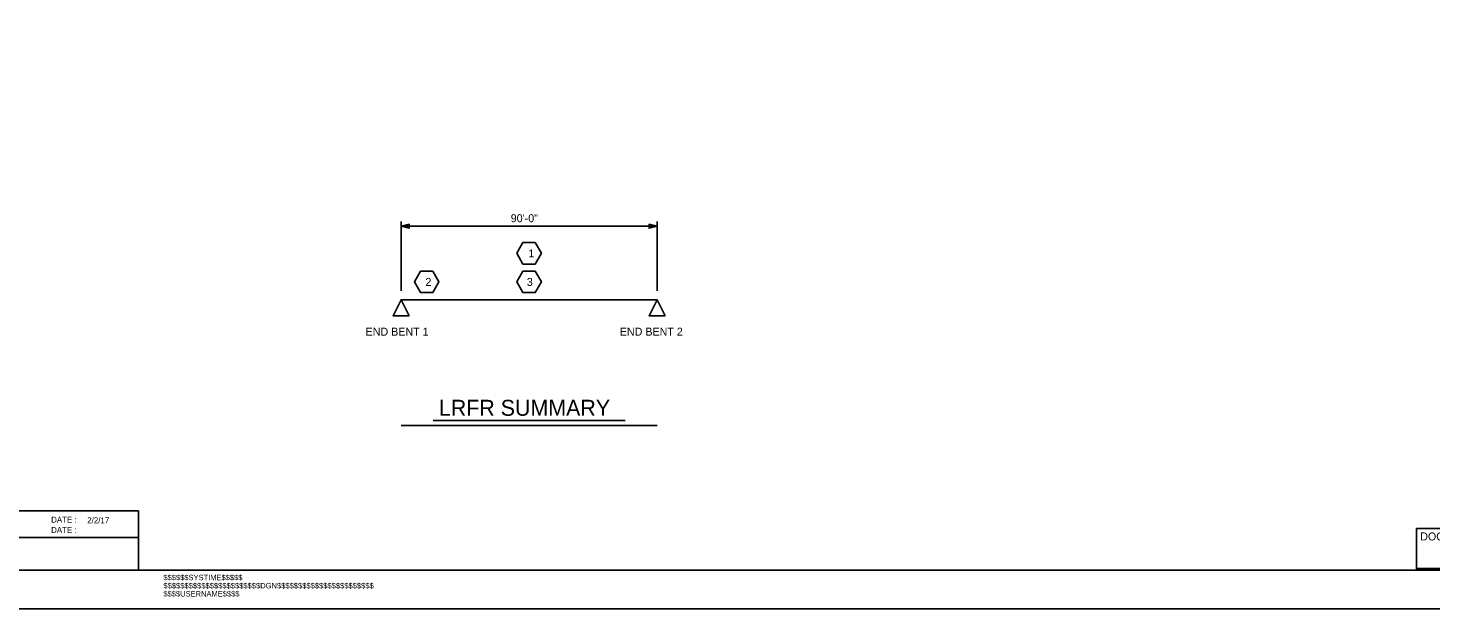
# Model space of a CAD drawing. Extents: x -169 to 381, y 285 to 620.
# Drawn here: x 28.2 to 247.3, y 284.7 to 375.4 of the extents above; entities that cross this region are included whole.
import ezdxf

# ---------------------------------------------------------------- set-up
doc = ezdxf.new("R2010")
doc.units = 0
for name, color, linetype in [('Arrowhead Terminators', 7, 'Continuous'), ('Dimension Lines', 7, 'Continuous'), ('Mis Object Lines', 7, 'Continuous'), ('Plan Sheet', 7, 'Continuous'), ('Plan Sheet CELL', 7, 'Continuous'), ('Plot Label CELL', 7, 'Continuous'), ('Plot Shape CELL', 7, 'Continuous'), ('Sheet Sticker Exception Certification CELL', 7, 'Continuous'), ('Sub End Bent Cap Lines CELL', 7, 'Continuous'), ('Table Border', 7, 'Continuous'), ('Text', 7, 'Continuous'), ('Title Text', 7, 'Continuous')]:
    doc.layers.add(name, color=color, linetype=linetype)

# ---------------------------------------------------------------- blocks, each defined once
blk = doc.blocks.new('AH')
at = {"layer": 'Sub End Bent Cap Lines CELL'}
blk.add_lwpolyline([(0, 0), (-1.25, 0.31), (-1.25, -0.31)], close=True, dxfattribs=at)

msp = doc.modelspace()

# ---------------------------------------------------------------- linework, layer by layer
at = {"layer": 'Dimension Lines'}
for p, q in [((86.45, 334.35), (86.45, 345.18)), ((86.45, 344.43), (126.45, 344.43)), ((126.45, 334.35), (126.45, 345.18))]:
    msp.add_line(p, q, dxfattribs=at)
at = {"layer": 'Mis Object Lines'}
msp.add_line((86.45, 332.96), (126.45, 332.96), dxfattribs=at)
for points in [[(87.7, 330.46), (85.2, 330.46), (86.45, 332.96)], [(127.7, 330.46), (125.2, 330.46), (126.45, 332.96)]]:
    msp.add_lwpolyline(points, close=True, dxfattribs=at)
at = {"layer": 'Plan Sheet'}
for p, q in [((3.77, 299.98), (45.41, 299.98)), ((45.41, 290.71), (45.41, 299.98)), ((45.41, 299.98), (45.41, 299.98)), ((45.41, 295.8), (3.77, 295.8))]:
    msp.add_line(p, q, dxfattribs=at)
at = {"layer": 'Plan Sheet CELL'}
msp.add_line((3.77, 290.71), (323.78, 290.71), dxfattribs=at)
at = {"layer": 'Plot Shape CELL'}
msp.add_lwpolyline([(-6.77, 504.65), (323.86, 504.65), (323.86, 284.65), (-6.77, 284.65)], close=True, dxfattribs=at)
at = {"layer": 'Sheet Sticker Exception Certification CELL'}
msp.add_lwpolyline([(245.07, 297.23), (273.56, 297.23), (273.56, 290.96), (245.07, 290.96)], close=True, dxfattribs=at)
at = {"layer": 'Table Border'}
for points in [[(107.41, 341.87), (105.49, 341.87), (104.53, 340.2), (105.49, 338.53), (107.41, 338.53), (108.37, 340.2)], [(91.41, 337.4), (89.49, 337.4), (88.53, 335.74), (89.49, 334.07), (91.41, 334.07), (92.37, 335.74)], [(107.41, 337.4), (105.49, 337.4), (104.53, 335.74), (105.49, 334.07), (107.41, 334.07), (108.37, 335.74)]]:
    msp.add_lwpolyline(points, close=True, dxfattribs=at)
at = {"layer": 'Title Text'}
for p, q in [((121.45, 314.07), (91.45, 314.07)), ((126.45, 313.32), (86.45, 313.32))]:
    msp.add_line(p, q, dxfattribs=at)

# ---------------------------------------------------------------- block references
at = {"layer": 'Arrowhead Terminators', "rotation": 180}
msp.add_blockref('AH', (86.45, 344.43), dxfattribs=at)
at = {"layer": 'Arrowhead Terminators'}
msp.add_blockref('AH', (126.45, 344.43), dxfattribs=at)

# ---------------------------------------------------------------- texts
at = {"layer": 'Plan Sheet'}
for p in [(31.79, 298.13), (31.79, 296.53)]:
    msp.add_text('DATE :', height=0.925, dxfattribs=at).set_placement(p)
at = {"layer": 'Plot Label CELL'}
for s, height, p in [('$$$$$$SYSTIME$$$$$', 0.8504, (49.33, 289.14)), ('$$$$$$$$$$$$$$$$$$$$$$$DGN$$$$$$$$$$$$$$$$$$$$$$$', 0.8556, (49.33, 287.86)), ('$$$$USERNAME$$$$', 0.8504, (49.33, 286.59))]:
    msp.add_text(s, height=height, dxfattribs=at).set_placement(p)
at = {"layer": 'Sheet Sticker Exception Certification CELL'}
msp.add_text('DOCUMENT NOT CONSIDERED', height=1.2472, dxfattribs=at).set_placement((245.66, 295.35))
at = {"layer": 'Text'}
for s, height, p in [('90\'-0"', 1.25, (103.58, 345.06)), ('1', 1.25, (106.34, 339.57)), ('2', 1.25, (90.26, 335.11)), ('3', 1.25, (106.1, 335.11)), ('END BENT 1', 1.25, (80.91, 327.34)), ('END BENT 2', 1.25, (120.62, 327.34)), ('2/2/17', 0.925, (37.43, 298.04))]:
    msp.add_text(s, height=height, dxfattribs=at).set_placement(p)
at = {"layer": 'Title Text'}
msp.add_text('LRFR SUMMARY', height=2.5, dxfattribs=at).set_placement((92.36, 314.82))

doc.saveas('drawing.dxf')
